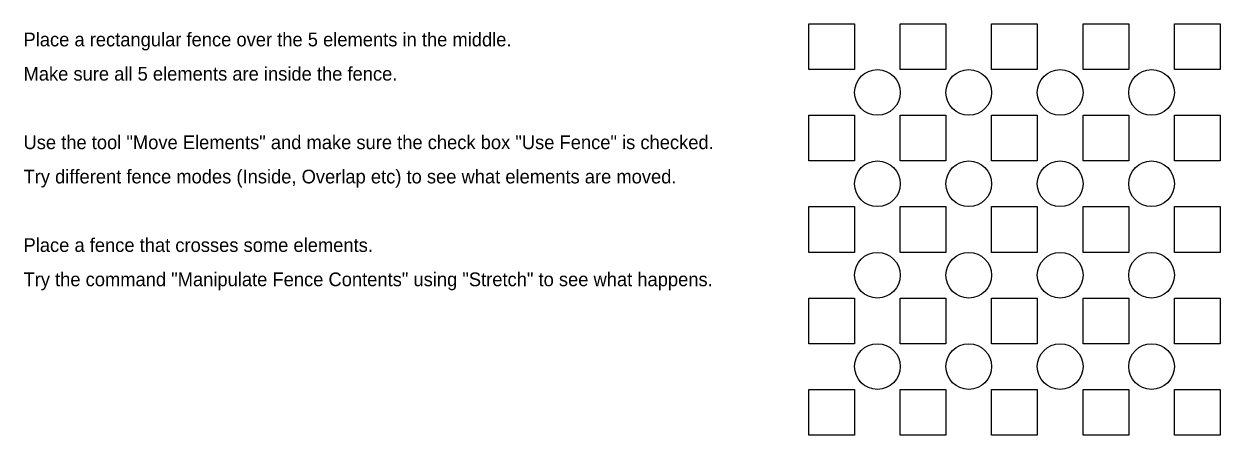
# Model space of a CAD drawing. Extents: x 1517704.4 to 1517730.6, y 6495367.3 to 6495376.3.
import ezdxf

# ---------------------------------------------------------------- set-up
doc = ezdxf.new("R2010")
doc.units = 0
doc.layers.add('Instruktioner', color=7, linetype='Continuous')
doc.layers.add('Lager 1', color=7, linetype='Continuous')

msp = doc.modelspace()

# ---------------------------------------------------------------- linework, layer by layer
at = {"layer": 'Lager 1'}
for points in [[(1517721.615, 6495376.27), (1517722.615, 6495376.27), (1517722.615, 6495375.27), (1517721.615, 6495375.27)], [(1517723.615, 6495376.27), (1517724.615, 6495376.27), (1517724.615, 6495375.27), (1517723.615, 6495375.27)], [(1517725.615, 6495376.27), (1517726.615, 6495376.27), (1517726.615, 6495375.27), (1517725.615, 6495375.27)], [(1517727.615, 6495376.27), (1517728.615, 6495376.27), (1517728.615, 6495375.27), (1517727.615, 6495375.27)], [(1517729.615, 6495376.27), (1517730.615, 6495376.27), (1517730.615, 6495375.27), (1517729.615, 6495375.27)], [(1517721.615, 6495374.27), (1517722.615, 6495374.27), (1517722.615, 6495373.27), (1517721.615, 6495373.27)], [(1517723.615, 6495374.27), (1517724.615, 6495374.27), (1517724.615, 6495373.27), (1517723.615, 6495373.27)], [(1517725.615, 6495374.27), (1517726.615, 6495374.27), (1517726.615, 6495373.27), (1517725.615, 6495373.27)], [(1517727.615, 6495374.27), (1517728.615, 6495374.27), (1517728.615, 6495373.27), (1517727.615, 6495373.27)], [(1517729.615, 6495374.27), (1517730.615, 6495374.27), (1517730.615, 6495373.27), (1517729.615, 6495373.27)], [(1517721.615, 6495372.27), (1517722.615, 6495372.27), (1517722.615, 6495371.27), (1517721.615, 6495371.27)], [(1517723.615, 6495372.27), (1517724.615, 6495372.27), (1517724.615, 6495371.27), (1517723.615, 6495371.27)], [(1517725.615, 6495372.27), (1517726.615, 6495372.27), (1517726.615, 6495371.27), (1517725.615, 6495371.27)], [(1517727.615, 6495372.27), (1517728.615, 6495372.27), (1517728.615, 6495371.27), (1517727.615, 6495371.27)], [(1517729.615, 6495372.27), (1517730.615, 6495372.27), (1517730.615, 6495371.27), (1517729.615, 6495371.27)], [(1517721.615, 6495370.27), (1517722.615, 6495370.27), (1517722.615, 6495369.27), (1517721.615, 6495369.27)], [(1517723.615, 6495370.27), (1517724.615, 6495370.27), (1517724.615, 6495369.27), (1517723.615, 6495369.27)], [(1517725.615, 6495370.27), (1517726.615, 6495370.27), (1517726.615, 6495369.27), (1517725.615, 6495369.27)], [(1517727.615, 6495370.27), (1517728.615, 6495370.27), (1517728.615, 6495369.27), (1517727.615, 6495369.27)], [(1517729.615, 6495370.27), (1517730.615, 6495370.27), (1517730.615, 6495369.27), (1517729.615, 6495369.27)], [(1517721.615, 6495368.27), (1517722.615, 6495368.27), (1517722.615, 6495367.27), (1517721.615, 6495367.27)], [(1517723.615, 6495368.27), (1517724.615, 6495368.27), (1517724.615, 6495367.27), (1517723.615, 6495367.27)], [(1517725.615, 6495368.27), (1517726.615, 6495368.27), (1517726.615, 6495367.27), (1517725.615, 6495367.27)], [(1517727.615, 6495368.27), (1517728.615, 6495368.27), (1517728.615, 6495367.27), (1517727.615, 6495367.27)], [(1517729.615, 6495368.27), (1517730.615, 6495368.27), (1517730.615, 6495367.27), (1517729.615, 6495367.27)]]:
    msp.add_lwpolyline(points, close=True, dxfattribs=at)
for centre in [(1517723.115, 6495374.77), (1517725.115, 6495374.77), (1517727.115, 6495374.77), (1517729.115, 6495374.77), (1517723.115, 6495372.77), (1517725.115, 6495372.77), (1517727.115, 6495372.77), (1517729.115, 6495372.77), (1517723.115, 6495370.77), (1517725.115, 6495370.77), (1517727.115, 6495370.77), (1517729.115, 6495370.77), (1517723.115, 6495368.77), (1517725.115, 6495368.77), (1517727.115, 6495368.77), (1517729.115, 6495368.77)]:
    msp.add_circle(centre, 0.5, dxfattribs=at)

# ---------------------------------------------------------------- texts
at = {"layer": 'Instruktioner'}
for s, p in [('Place a rectangular fence over the 5 elements in the middle.', (1517704.424, 6495375.779)), ('Make sure all 5 elements are inside the fence.', (1517704.424, 6495375.029)), ('Use the tool "Move Elements" and make sure the check box "Use Fence" is checked.', (1517704.424, 6495373.529)), ('Try different fence modes (Inside, Overlap etc) to see what elements are moved.', (1517704.424, 6495372.779)), ('Place a fence that crosses some elements.', (1517704.424, 6495371.279)), ('Try the command "Manipulate Fence Contents" using "Stretch" to see what happens.', (1517704.424, 6495370.529))]:
    msp.add_text(s, height=0.3, dxfattribs=at).set_placement(p)

doc.saveas('drawing.dxf')
